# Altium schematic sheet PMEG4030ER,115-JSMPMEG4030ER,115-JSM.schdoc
size 127 x 101 mm
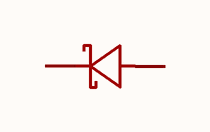
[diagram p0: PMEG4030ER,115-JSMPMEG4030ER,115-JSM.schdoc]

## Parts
D?  pmeg4030er,115-jsm  [SOD-123FL_L2.8-W1.9-LS3.7-RD]  (value not drawn)

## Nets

Not connected (* = marked no-connect by the designer): D? 1(C) 2(A)

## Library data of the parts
D? = pmeg4030er,115-jsm: 二极管配置:1个独立式;正向压降(Vf):550mV@3A;直流反向耐压(Vr):40V;整流电流:3A;; Manufacturer: JSMSEMI(杰盛微); AddInBom: yes; ModelId: ee80cc4b5e2f4a0b8a944bbfc66c96ba; ModelTransform: 141.732,74.803,0,0,0,0,0,0,0; Diode Configuration: 1个独立式; Voltage - DC Reverse(Vr): 40V; Current - Rectified: 3A; Reverse Leakage Current (Ir): 100uA@40V; Operating Junction Temperature Range: -65℃~+150℃; Non-Repetitive Peak Forward Surge Current: 80A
